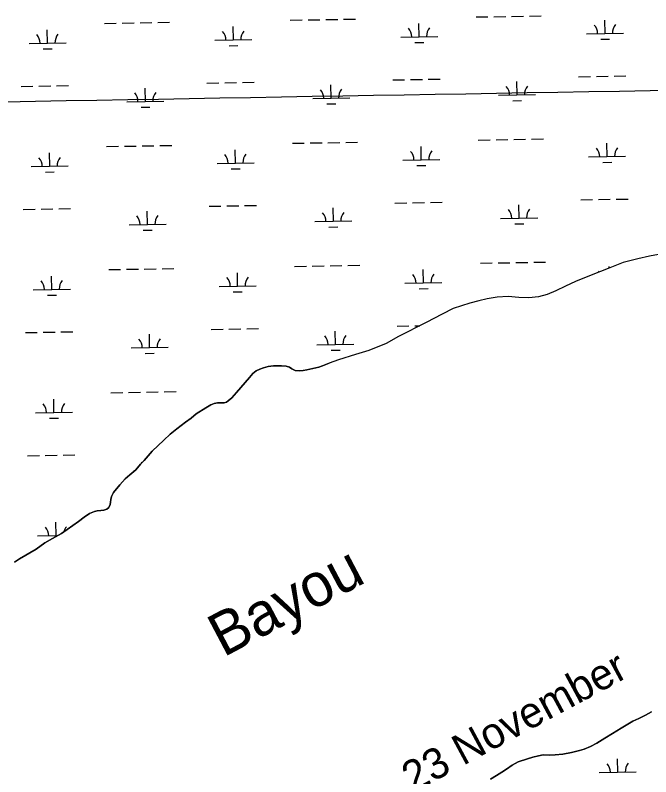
# Model space of a CAD drawing. Extents: x 3892998 to 3931244, y 278583 to 304547.
# Drawn here: x 3915597 to 3917313, y 294629 to 296687 of the extents above; entities that cross this region are included whole.
import ezdxf

# ---------------------------------------------------------------- set-up
doc = ezdxf.new("R2010")
doc.units = 0
for name, color, linetype in [('V-GRID-MAJR', 7, 'Continuous'), ('V-RIVR-IDEN', 7, 'Continuous'), ('V-TOPO-SHOR', 7, 'Continuous'), ('V-WETL-SWMP', 7, 'Continuous')]:
    doc.layers.add(name, color=color, linetype=linetype)

msp = doc.modelspace()

# ---------------------------------------------------------------- linework, layer by layer
at = {"layer": 'V-GRID-MAJR'}
msp.add_spline([(3897060.6180000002, 296135.19), (3902372.4110000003, 296225.205), (3907684.191, 296315.993), (3912995.9590000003, 296407.553), (3918307.7120000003, 296499.886), (3923619.453, 296592.991), (3928931.179, 296686.869), (3928931.18, 296686.869)], degree=3, dxfattribs=at)
at = {"layer": 'V-TOPO-SHOR'}
for points in [[(3917344.292, 296042.517), (3917309.995, 296035.685), (3917278.273, 296029.031), (3917239.193, 296018.482), (3917202.6610000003, 296004.746), (3917147.457, 295983.054), (3917109.721, 295967.544), (3917083.095, 295955.107), (3917057.054, 295941.87200000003), (3917033.818, 295932.177), (3917009.819, 295926.246), (3916984.465, 295923.498), (3916957.356, 295924.124), (3916927.889, 295926.555), (3916898.588, 295925.42100000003), (3916871.237, 295920.907), (3916848.629, 295915.36100000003), (3916824.828, 295909.231), (3916779.5810000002, 295894.779), (3916750.356, 295879.39400000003), (3916706.6210000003, 295856.614), (3916631.879, 295818.466), (3916598.8680000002, 295799.749), (3916551.995, 295780.56), (3916516.284, 295770.178), (3916470.247, 295756.127), (3916444.62, 295746.663)], [(3915922.335, 295458.94), (3915935.744, 295473.902), (3915944.943, 295484.208), (3915956.1010000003, 295496.695), (3915966.961, 295509.177), (3915998.41, 295538.935), (3916015.163, 295555.003), (3916033.798, 295569.308), (3916056.549, 295587.089), (3916072.149, 295598.419), (3916085.577, 295610.23), (3916111.691, 295626.255), (3916124.946, 295634.124), (3916134.381, 295638.222), (3916143.634, 295639.756), (3916153.5870000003, 295639.719), (3916161.5700000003, 295639.473), (3916167.473, 295641.48), (3916172.378, 295644.96), (3916182.181, 295653.201), (3916194.41, 295667.465), (3916229.83, 295708.482), (3916238.833, 295718.884), (3916248.051, 295726.134), (3916257.878, 295730.826), (3916267.806, 295734.43700000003), (3916280.1070000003, 295737.47000000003), (3916294.381, 295739.82300000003), (3916315.865, 295739.759), (3916328.98, 295738.363), (3916337.3710000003, 295735.95), (3916344.393, 295731.756), (3916352.698, 295727.373), (3916364.236, 295725.868), (3916374.282, 295726.914), (3916384.52, 295728.653), (3916417.095, 295735.555), (3916427.026, 295739.264), (3916444.62, 295746.663)], [(3915594.836, 295209.176), (3915608.578, 295218.228), (3915653.943, 295244.426), (3915676.502, 295261.515), (3915697.913, 295272.979), (3915722.27, 295286.533), (3915768.09, 295319.039), (3915783.29, 295331.056), (3915797.522, 295340.211), (3915810.988, 295346.011), (3915818.6610000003, 295347.832), (3915828.414, 295348.483), (3915835.9960000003, 295349.417), (3915844.255, 295352.325), (3915849.355, 295356.396), (3915853.344, 295364.797), (3915854.487, 295371.20900000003), (3915855.13, 295378.801), (3915857.15, 295386.699), (3915862.306, 295397.471), (3915879.2290000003, 295417.779), (3915894.108, 295434.032), (3915906.453, 295445.439), (3915922.335, 295458.94)], [(3917315.1350000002, 294804.63), (3917299.486, 294795.33), (3917280.731, 294786.61), (3917265.068, 294779.311), (3917233.5670000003, 294760.80700000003), (3917210.247, 294745.855), (3917189.611, 294733.82300000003), (3917167.886, 294720.281), (3917150.83, 294711.373), (3917133.068, 294704.059), (3917120.485, 294700.379), (3917099.309, 294694.74700000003), (3917076.123, 294690.7), (3917055.4280000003, 294688.173), (3917039.923, 294687.776), (3917023.211, 294688.273), (3917010.018, 294686.291), (3916994.934, 294682.395), (3916980.355, 294677.904), (3916955.191, 294670.044), (3916938.94, 294660.74), (3916923.799, 294650.041), (3916911.446, 294641.761), (3916896.997, 294632.267), (3916880.2460000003, 294622.858)]]:
    msp.add_lwpolyline(points, dxfattribs=at)
at = {"layer": 'V-WETL-SWMP'}
for p, q in [((3916937.644457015, 296683.813876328), (3916969.639663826, 296684.3677184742)), ((3916985.637267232, 296684.6446395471), (3917017.632474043, 296685.19848169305)), ((3915837.993195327, 296664.7787371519), (3915869.988402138, 296665.332579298)), ((3915885.9860055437, 296665.60950037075), (3915917.9812123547, 296666.1633425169)), ((3915933.9788157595, 296666.44026358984), (3915965.9740225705, 296666.994105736)), ((3915981.9716259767, 296667.271026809), (3916013.9668327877, 296667.8248689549)), ((3916339.826015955, 296673.4655435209), (3916371.821222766, 296674.0193856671)), ((3916387.818826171, 296674.2963067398), (3916419.814032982, 296674.850148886)), ((3916435.811636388, 296675.12706995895), (3916467.806843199, 296675.6809121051)), ((3916483.8044466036, 296675.95783317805), (3916515.799653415, 296676.51167532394)), ((3916687.968213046, 296628.7423389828), (3916687.3451406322, 296664.736946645)), ((3916841.658836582, 296682.15234989), (3916873.654043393, 296682.70619203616)), ((3916889.651646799, 296682.9831131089), (3916921.64685361, 296683.536955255)), ((3917189.8010336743, 296637.42914535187), (3917189.17796126, 296673.42375301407)), ((3915684.3025717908, 296611.3687262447), (3915683.679499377, 296647.3633339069)), ((3916186.135392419, 296620.05553261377), (3916185.5123200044, 296656.05014027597)), ((3916637.975702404, 296627.8769606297), (3916737.9607236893, 296629.6077173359)), ((3917139.8085230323, 296636.56376699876), (3917239.793544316, 296638.29452370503)), ((3915634.310061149, 296610.50334789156), (3915734.2950824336, 296612.2341045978)), ((3916136.1428817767, 296619.19015426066), (3916236.127903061, 296620.9209109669)), ((3916174.404262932, 296604.4191531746), (3916198.4006680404, 296604.8345347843)), ((3916676.2370835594, 296613.1059595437), (3916700.2334886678, 296613.52134115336)), ((3917178.069904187, 296621.7927659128), (3917202.0663092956, 296622.20814752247)), ((3915672.571442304, 296595.73234680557), (3915696.567847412, 296596.14772841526)), ((3917118.401876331, 296520.7439217), (3917150.3970831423, 296521.29776384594)), ((3917166.3946865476, 296521.5746849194), (3917198.389893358, 296522.12852706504)), ((3917214.3874967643, 296522.40544813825), (3917246.3827035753, 296522.9592902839)), ((3916114.7362350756, 296503.3703089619), (3916146.731441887, 296503.9241511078)), ((3916162.729045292, 296504.2010721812), (3916194.724252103, 296504.7549143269)), ((3916210.721855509, 296505.0318354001), (3916242.7170623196, 296505.5856775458)), ((3916616.5690557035, 296512.05711533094), (3916648.564262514, 296512.61095747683)), ((3916664.5618659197, 296512.8878785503), (3916696.557072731, 296513.441720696)), ((3916712.554676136, 296513.7186417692), (3916744.549882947, 296514.27248391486)), ((3916952.1664907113, 296471.42940493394), (3916951.543418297, 296507.4240125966)), ((3915612.903414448, 296494.6835025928), (3915644.898621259, 296495.23734473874)), ((3915660.8962246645, 296495.5142658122), (3915692.8914314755, 296496.06810795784)), ((3915708.889034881, 296496.34502903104), (3915740.884241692, 296496.8988711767)), ((3915948.500849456, 296454.0557921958), (3915947.8777770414, 296490.0503998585)), ((3916450.3336700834, 296462.7425985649), (3916449.7105976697, 296498.73720622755)), ((3916400.341159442, 296461.8772202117), (3916500.326180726, 296463.60797691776)), ((3916902.1739800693, 296470.56402658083), (3917002.159001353, 296472.2947832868)), ((3915898.5083388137, 296453.1904138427), (3915998.493360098, 296454.9211705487)), ((3915936.769719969, 296438.4194127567), (3915960.7661250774, 296438.8347943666)), ((3916438.602540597, 296447.10621912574), (3916462.5989457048, 296447.52160073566)), ((3916940.435361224, 296455.79302549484), (3916964.4317663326, 296456.2084071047)), ((3915987.729420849, 296334.6458572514), (3916019.7246276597, 296335.1996993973)), ((3916345.583810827, 296340.84037396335), (3916377.579017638, 296341.39421610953)), ((3916393.576621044, 296341.6711371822), (3916425.5718278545, 296342.2249793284)), ((3916441.56943126, 296342.5019004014), (3916473.564638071, 296343.0557425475)), ((3916489.5622414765, 296343.3326636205), (3916521.557448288, 296343.8865057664)), ((3916847.416631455, 296349.5271803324), (3916879.411838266, 296350.0810224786)), ((3916895.4094416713, 296350.3579435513), (3916927.4046484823, 296350.91178569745)), ((3916943.402251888, 296351.1887067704), (3916975.3974586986, 296351.7425489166)), ((3916991.3950621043, 296352.0194699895), (3917023.3902689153, 296352.5733121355)), ((3917195.5588285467, 296304.80397579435), (3917194.935756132, 296340.79858345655)), ((3915690.0603666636, 296278.74355668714), (3915689.4372942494, 296314.73816434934)), ((3915843.7509902, 296332.1535675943), (3915875.7461970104, 296332.7074097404)), ((3915891.743800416, 296332.98433081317), (3915923.739007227, 296333.53817295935)), ((3915939.7366106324, 296333.81509403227), (3915971.7318174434, 296334.36893617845)), ((3916191.8931872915, 296287.4303630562), (3916191.270114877, 296323.4249707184)), ((3916693.726007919, 296296.11716942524), (3916693.102935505, 296332.11177708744)), ((3916643.733497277, 296295.25179107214), (3916743.718518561, 296296.98254777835)), ((3917145.5663179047, 296303.9385974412), (3917245.551339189, 296305.66935414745)), ((3915640.0678560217, 296277.878178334), (3915740.052877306, 296279.60893504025)), ((3916141.900676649, 296286.5649847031), (3916241.885697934, 296288.2957414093)), ((3916681.9948784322, 296280.48078998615), (3916705.99128354, 296280.89617159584)), ((3917183.8276990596, 296289.1675963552), (3917207.824104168, 296289.5829779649)), ((3915678.329237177, 296263.107177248), (3915702.325642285, 296263.5225588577)), ((3916180.1620578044, 296271.7939836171), (3916204.158462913, 296272.20936522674)), ((3916120.4940299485, 296170.7451394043), (3916152.4892367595, 296171.2989815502)), ((3916168.4868401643, 296171.57590262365), (3916200.4820469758, 296172.12974476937)), ((3916216.479650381, 296172.4066658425), (3916248.474857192, 296172.96050798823)), ((3916622.3268505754, 296179.43194577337), (3916654.322057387, 296179.9857879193)), ((3916670.3196607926, 296180.2627089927), (3916702.3148676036, 296180.8165511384)), ((3916718.312471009, 296181.0934722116), (3916750.30767782, 296181.6473143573)), ((3916957.9242855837, 296138.80423537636), (3916957.3012131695, 296174.798843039)), ((3917124.1596712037, 296188.1187521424), (3917156.1548780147, 296188.67259428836)), ((3917172.1524814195, 296188.9495153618), (3917204.147688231, 296189.50335750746)), ((3917220.1452916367, 296189.78027858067), (3917252.1404984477, 296190.33412072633)), ((3915618.66120932, 296162.0583330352), (3915650.6564161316, 296162.61217518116)), ((3915666.654019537, 296162.8890962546), (3915698.649226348, 296163.44293840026)), ((3915714.6468297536, 296163.71985947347), (3915746.6420365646, 296164.2737016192)), ((3915954.258644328, 296121.4306226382), (3915953.6355719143, 296157.4252303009)), ((3916456.0914649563, 296130.1174290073), (3916455.468392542, 296166.11203667)), ((3916406.0989543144, 296129.2520506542), (3916506.083975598, 296130.9828073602)), ((3916907.931774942, 296137.93885702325), (3917007.9167962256, 296139.66961372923)), ((3915904.2661336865, 296120.5652442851), (3916004.2511549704, 296122.29600099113)), ((3916444.3603354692, 296114.48104956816), (3916468.356740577, 296114.8964311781)), ((3916946.193156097, 296123.16785593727), (3916970.189561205, 296123.58323754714)), ((3915942.5275148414, 296105.7942431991), (3915966.52391995, 296106.20962480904)), ((3916351.3416056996, 296008.2152044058), (3916383.3368125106, 296008.76904655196)), ((3916399.3344159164, 296009.0459676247), (3916431.3296227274, 296009.5998097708)), ((3916447.3272261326, 296009.8767308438), (3916479.3224329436, 296010.4305729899)), ((3916495.3200363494, 296010.7074940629), (3916527.3152431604, 296011.26133620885)), ((3916853.174426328, 296016.9020107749), (3916885.169633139, 296017.455852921)), ((3916901.1672365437, 296017.73277399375), (3916933.1624433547, 296018.28661613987)), ((3916949.1600467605, 296018.56353721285), (3916981.1552535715, 296019.117379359)), ((3916997.1528569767, 296019.39430043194), (3917029.148063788, 296019.9481425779)), ((3917200.765788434, 296004.0002907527), (3917200.693551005, 296008.17341389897)), ((3915849.5087850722, 295999.5283980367), (3915881.5039918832, 296000.0822401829)), ((3915897.5015952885, 296000.3591612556), (3915929.4968020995, 296000.9130034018)), ((3915945.4944055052, 296001.18992447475), (3915977.4896123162, 296001.7437666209)), ((3915993.487215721, 296002.02068769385), (3916025.4824225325, 296002.57452983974)), ((3916197.6509821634, 295954.8051934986), (3916197.0279097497, 295990.7998011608)), ((3916699.4838027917, 295963.49199986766), (3916698.8607303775, 295999.48660752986)), ((3915695.8181615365, 295946.11838712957), (3915695.195089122, 295982.11299479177)), ((3916649.4912921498, 295962.62662151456), (3916749.4763134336, 295964.3573782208)), ((3915645.825650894, 295945.25300877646), (3915745.8106721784, 295946.98376548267)), ((3916147.6584715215, 295953.9398151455), (3916247.6434928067, 295955.6705718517)), ((3916687.7526733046, 295947.85562042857), (3916711.749078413, 295948.27100203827)), ((3915684.0870320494, 295930.4820076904), (3915708.083437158, 295930.8973893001)), ((3916185.919852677, 295939.1688140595), (3916209.9162577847, 295939.58419566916)), ((3916628.084645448, 295846.8067762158), (3916660.0798522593, 295847.36061836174)), ((3916676.0774556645, 295847.6375394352), (3916689.4888227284, 295847.86969234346)), ((3915624.4190041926, 295829.4331634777), (3915656.414211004, 295829.9870056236)), ((3915672.4118144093, 295830.263926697), (3915704.4070212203, 295830.8177688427)), ((3915720.4046246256, 295831.0946899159), (3915752.3998314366, 295831.6485320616)), ((3915960.0164392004, 295788.8054530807), (3915959.3933667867, 295824.80006074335)), ((3916126.2518248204, 295838.11996984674), (3916158.2470316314, 295838.67381199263)), ((3916174.2446350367, 295838.95073306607), (3916206.239841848, 295839.5045752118)), ((3916222.2374452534, 295839.781496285), (3916254.2326520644, 295840.33533843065)), ((3916461.8492598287, 295797.49225944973), (3916461.226187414, 295833.4868671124)), ((3915910.023928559, 295787.9400747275), (3916010.0089498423, 295789.67083143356)), ((3916411.8567491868, 295796.6268810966), (3916511.8417704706, 295798.3576378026)), ((3916450.1181303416, 295781.8558800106), (3916474.1145354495, 295782.2712616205)), ((3915948.285309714, 295773.16907364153), (3915972.2817148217, 295773.58445525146)), ((3915855.2665799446, 295666.90322847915), (3915887.2617867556, 295667.4570706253)), ((3915903.2593901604, 295667.733991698), (3915935.2545969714, 295668.2878338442)), ((3915951.2522003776, 295668.56475491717), (3915983.2474071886, 295669.1185970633)), ((3915999.2450105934, 295669.39551813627), (3916031.240217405, 295669.94936028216)), ((3915701.5759564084, 295613.493217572), (3915700.952883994, 295649.4878252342)), ((3915651.5834457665, 295612.6278392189), (3915751.568467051, 295614.3585959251)), ((3915689.8448269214, 295597.85683813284), (3915713.84123203, 295598.27221974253)), ((3915630.176799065, 295496.8079939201), (3915662.1720058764, 295497.361836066)), ((3915678.1696092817, 295497.63875713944), (3915710.1648160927, 295498.1925992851)), ((3915726.1624194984, 295498.4695203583), (3915758.1576263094, 295499.023362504)), ((3915915.781723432, 295455.31490516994), (3915918.1181223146, 295455.3553486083)), ((3915707.333751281, 295280.8680480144), (3915706.7106788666, 295316.8626556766)), ((3915657.341240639, 295280.0026696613), (3915712.2433396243, 295280.9530337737)), ((3917224.347802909, 294641.67812800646), (3917223.7247304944, 294677.67273566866)), ((3917174.3552922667, 294640.81274965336), (3917274.340313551, 294642.54350635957))]:
    msp.add_line(p, q, dxfattribs=at)
for points in [[(3917344.292, 296042.517), (3917309.995, 296035.686), (3917278.273, 296029.032), (3917239.194, 296018.482), (3917202.6610000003, 296004.745), (3917147.457, 295983.053), (3917109.721, 295967.544), (3917083.095, 295955.107), (3917057.055, 295941.873), (3917033.8170000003, 295932.177), (3917009.819, 295926.24700000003), (3916984.464, 295923.49700000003), (3916957.356, 295924.125), (3916927.8880000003, 295926.555), (3916898.588, 295925.42100000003), (3916871.238, 295920.906), (3916848.629, 295915.36100000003), (3916824.828, 295909.232), (3916779.5810000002, 295894.778), (3916750.356, 295879.39400000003), (3916706.6210000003, 295856.614), (3916631.88, 295818.466), (3916598.867, 295799.75), (3916551.9960000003, 295780.56), (3916516.284, 295770.179), (3916470.248, 295756.127), (3916444.62, 295746.664), (3916427.026, 295739.263), (3916417.096, 295735.555), (3916384.52, 295728.653), (3916374.282, 295726.915), (3916364.237, 295725.867), (3916352.698, 295727.373), (3916344.393, 295731.756), (3916337.3710000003, 295735.95), (3916328.98, 295738.362), (3916315.864, 295739.759), (3916294.381, 295739.82300000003), (3916280.1070000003, 295737.469), (3916267.807, 295734.436), (3916257.877, 295730.827), (3916248.051, 295726.135), (3916238.833, 295718.885), (3916229.8310000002, 295708.482), (3916194.4110000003, 295667.465), (3916182.181, 295653.2), (3916172.377, 295644.96), (3916167.472, 295641.48), (3916161.571, 295639.473), (3916153.588, 295639.719), (3916143.634, 295639.756), (3916134.381, 295638.221), (3916124.946, 295634.123), (3916111.691, 295626.256), (3916085.577, 295610.229), (3916072.149, 295598.419), (3916056.5500000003, 295587.089), (3916033.798, 295569.309), (3916015.163, 295555.003), (3915998.4110000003, 295538.935), (3915966.961, 295509.178), (3915956.1, 295496.694), (3915944.943, 295484.208), (3915935.7430000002, 295473.903), (3915922.335, 295458.94), (3915906.454, 295445.44), (3915894.108, 295434.031), (3915879.23, 295417.778), (3915862.307, 295397.471), (3915857.15, 295386.69800000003), (3915855.13, 295378.802)], [(3915855.13, 295378.802), (3915854.487, 295371.21), (3915853.344, 295364.798), (3915849.355, 295356.397), (3915844.256, 295352.325), (3915835.9960000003, 295349.416), (3915828.414, 295348.483), (3915818.662, 295347.831), (3915810.987, 295346.01), (3915797.522, 295340.211), (3915783.29, 295331.05700000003), (3915768.09, 295319.039), (3915722.27, 295286.532), (3915697.914, 295272.98), (3915676.502, 295261.515), (3915653.943, 295244.426), (3915608.577, 295218.228), (3915594.836, 295209.176)], [(3917039.923, 294687.776), (3917055.4280000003, 294688.172), (3917076.123, 294690.701), (3917099.309, 294694.746), (3917120.485, 294700.379), (3917133.068, 294704.059), (3917150.8310000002, 294711.37200000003), (3917167.8850000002, 294720.282), (3917189.612, 294733.822), (3917210.247, 294745.855), (3917233.5670000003, 294760.80700000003), (3917265.068, 294779.31), (3917280.73, 294786.61), (3917299.486, 294795.33), (3917315.136, 294804.631)], [(3916880.2460000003, 294622.859), (3916896.9960000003, 294632.267), (3916911.4450000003, 294641.761), (3916923.8000000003, 294650.041), (3916938.941, 294660.74), (3916955.191, 294670.044), (3916980.355, 294677.904), (3916994.935, 294682.396), (3917010.018, 294686.291), (3917023.2120000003, 294688.273), (3917039.923, 294687.776)]]:
    msp.add_lwpolyline(points, dxfattribs=at)
for centre, radius, start, end in [((3916241.361836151, 296621.4863854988), 35.246287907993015, 140.21987699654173, 181.76353532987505), ((3916632.725333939, 296628.2609502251), 35.24628790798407, 0.21988000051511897, 41.76353833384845), ((3916743.1946567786, 296630.1731918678), 35.246287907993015, 140.21987699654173, 181.76353532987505), ((3917134.5581545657, 296636.94775659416), 35.24628790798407, 0.21988000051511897, 41.76353833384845), ((3917245.0274774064, 296638.8599982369), 35.246287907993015, 140.21987699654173, 181.76353532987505), ((3915629.059692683, 296610.887337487), 35.24628790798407, 0.21988000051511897, 41.76353833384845), ((3915739.529015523, 296612.7995791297), 35.246287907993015, 140.21987699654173, 181.76353532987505), ((3916130.8925133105, 296619.57414385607), 35.24628790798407, 0.21988000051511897, 41.76353833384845), ((3916395.0907909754, 296462.2612098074), 35.24628790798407, 0.21988000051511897, 41.76353833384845), ((3916505.5601138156, 296464.1734514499), 35.246287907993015, 140.21987699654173, 181.76353532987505), ((3916896.9236116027, 296470.94801617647), 35.24628790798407, 0.21988000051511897, 41.76353833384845), ((3917007.392934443, 296472.86025781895), 35.246287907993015, 140.21987699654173, 181.76353532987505), ((3915893.2579703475, 296453.5744034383), 35.24628790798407, 0.21988000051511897, 41.76353833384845), ((3916003.7272931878, 296455.4866450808), 35.246287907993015, 140.21987699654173, 181.76353532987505), ((3916638.4831288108, 296295.63578066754), 35.24628790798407, 0.21988000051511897, 41.76353833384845), ((3916748.952451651, 296297.54802231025), 35.246287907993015, 140.21987699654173, 181.76353532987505), ((3917140.3159494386, 296304.32258703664), 35.24628790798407, 0.21988000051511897, 41.76353833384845), ((3917250.785272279, 296306.23482867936), 35.246287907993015, 140.21987699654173, 181.76353532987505), ((3915634.8174875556, 296278.26216792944), 35.24628790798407, 0.21988000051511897, 41.76353833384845), ((3915745.286810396, 296280.17440957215), 35.246287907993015, 140.21987699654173, 181.76353532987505), ((3916136.6503081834, 296286.9489742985), 35.24628790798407, 0.21988000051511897, 41.76353833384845), ((3916247.1196310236, 296288.8612159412), 35.246287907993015, 140.21987699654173, 181.76353532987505), ((3916400.8485858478, 296129.63604024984), 35.24628790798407, 0.21988000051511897, 41.76353833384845), ((3916511.3179086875, 296131.5482818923), 35.246287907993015, 140.21987699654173, 181.76353532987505), ((3916902.681406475, 296138.3228466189), 35.24628790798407, 0.21988000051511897, 41.76353833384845), ((3917013.150729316, 296140.23508826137), 35.246287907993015, 140.21987699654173, 181.76353532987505), ((3915899.01576522, 296120.9492338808), 35.24628790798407, 0.21988000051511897, 41.76353833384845), ((3916009.4850880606, 296122.8614755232), 35.246287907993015, 140.21987699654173, 181.76353532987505), ((3916644.240923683, 295963.01061110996), 35.24628790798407, 0.21988000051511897, 41.76353833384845), ((3916754.710246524, 295964.9228527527), 35.246287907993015, 140.21987699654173, 181.76353532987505), ((3917146.0737443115, 295971.69741747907), 35.24628790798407, 38.041081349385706, 41.76353833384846), ((3915640.575282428, 295945.63699837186), 35.24628790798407, 0.21988000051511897, 41.76353833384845), ((3915751.0446052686, 295947.5492400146), 35.246287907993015, 140.21987699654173, 181.76353532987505), ((3916142.4081030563, 295954.3238047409), 35.24628790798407, 0.21988000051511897, 41.76353833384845), ((3916252.877425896, 295956.2360463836), 35.246287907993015, 140.21987699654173, 181.76353532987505), ((3916406.60638072, 295797.01087069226), 35.24628790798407, 0.21988000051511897, 41.76353833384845), ((3916517.07570356, 295798.92311233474), 35.246287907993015, 140.21987699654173, 181.76353532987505), ((3915904.773560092, 295788.3240643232), 35.24628790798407, 0.21988000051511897, 41.76353833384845), ((3916015.2428829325, 295790.2363059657), 35.246287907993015, 140.21987699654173, 181.76353532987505), ((3915646.3330773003, 295613.0118288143), 35.24628790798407, 0.21988000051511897, 41.76353833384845), ((3915756.802400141, 295614.924070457), 35.246287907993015, 140.21987699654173, 181.76353532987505), ((3915910.5313549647, 295455.69889476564), 35.24628790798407, 37.31159322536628, 41.76353833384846), ((3915652.0908721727, 295280.3866592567), 35.24628790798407, 0.21988000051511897, 41.76353833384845), ((3915762.560195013, 295282.2989008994), 35.246287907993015, 140.2198769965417, 165.94415836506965), ((3917169.1049238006, 294641.19673924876), 35.24628790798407, 0.21988000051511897, 41.76353833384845), ((3917279.5742466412, 294643.10898089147), 35.246287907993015, 140.21987699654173, 181.76353532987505)]:
    msp.add_arc(centre, radius, start, end, dxfattribs=at)

# ---------------------------------------------------------------- texts
at = {"layer": 'V-RIVR-IDEN'}
for s, height, rotation, p in [('Bayou', 116.00050399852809, 27.840459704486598, (3916159.076611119, 294951.0980236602)), ('23 November', 82.99983200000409, 28.30392232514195, (3916670.293000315, 294585.14651463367))]:
    msp.add_text(s, height=height, rotation=rotation, dxfattribs=at).set_placement(p)

doc.saveas('drawing.dxf')
